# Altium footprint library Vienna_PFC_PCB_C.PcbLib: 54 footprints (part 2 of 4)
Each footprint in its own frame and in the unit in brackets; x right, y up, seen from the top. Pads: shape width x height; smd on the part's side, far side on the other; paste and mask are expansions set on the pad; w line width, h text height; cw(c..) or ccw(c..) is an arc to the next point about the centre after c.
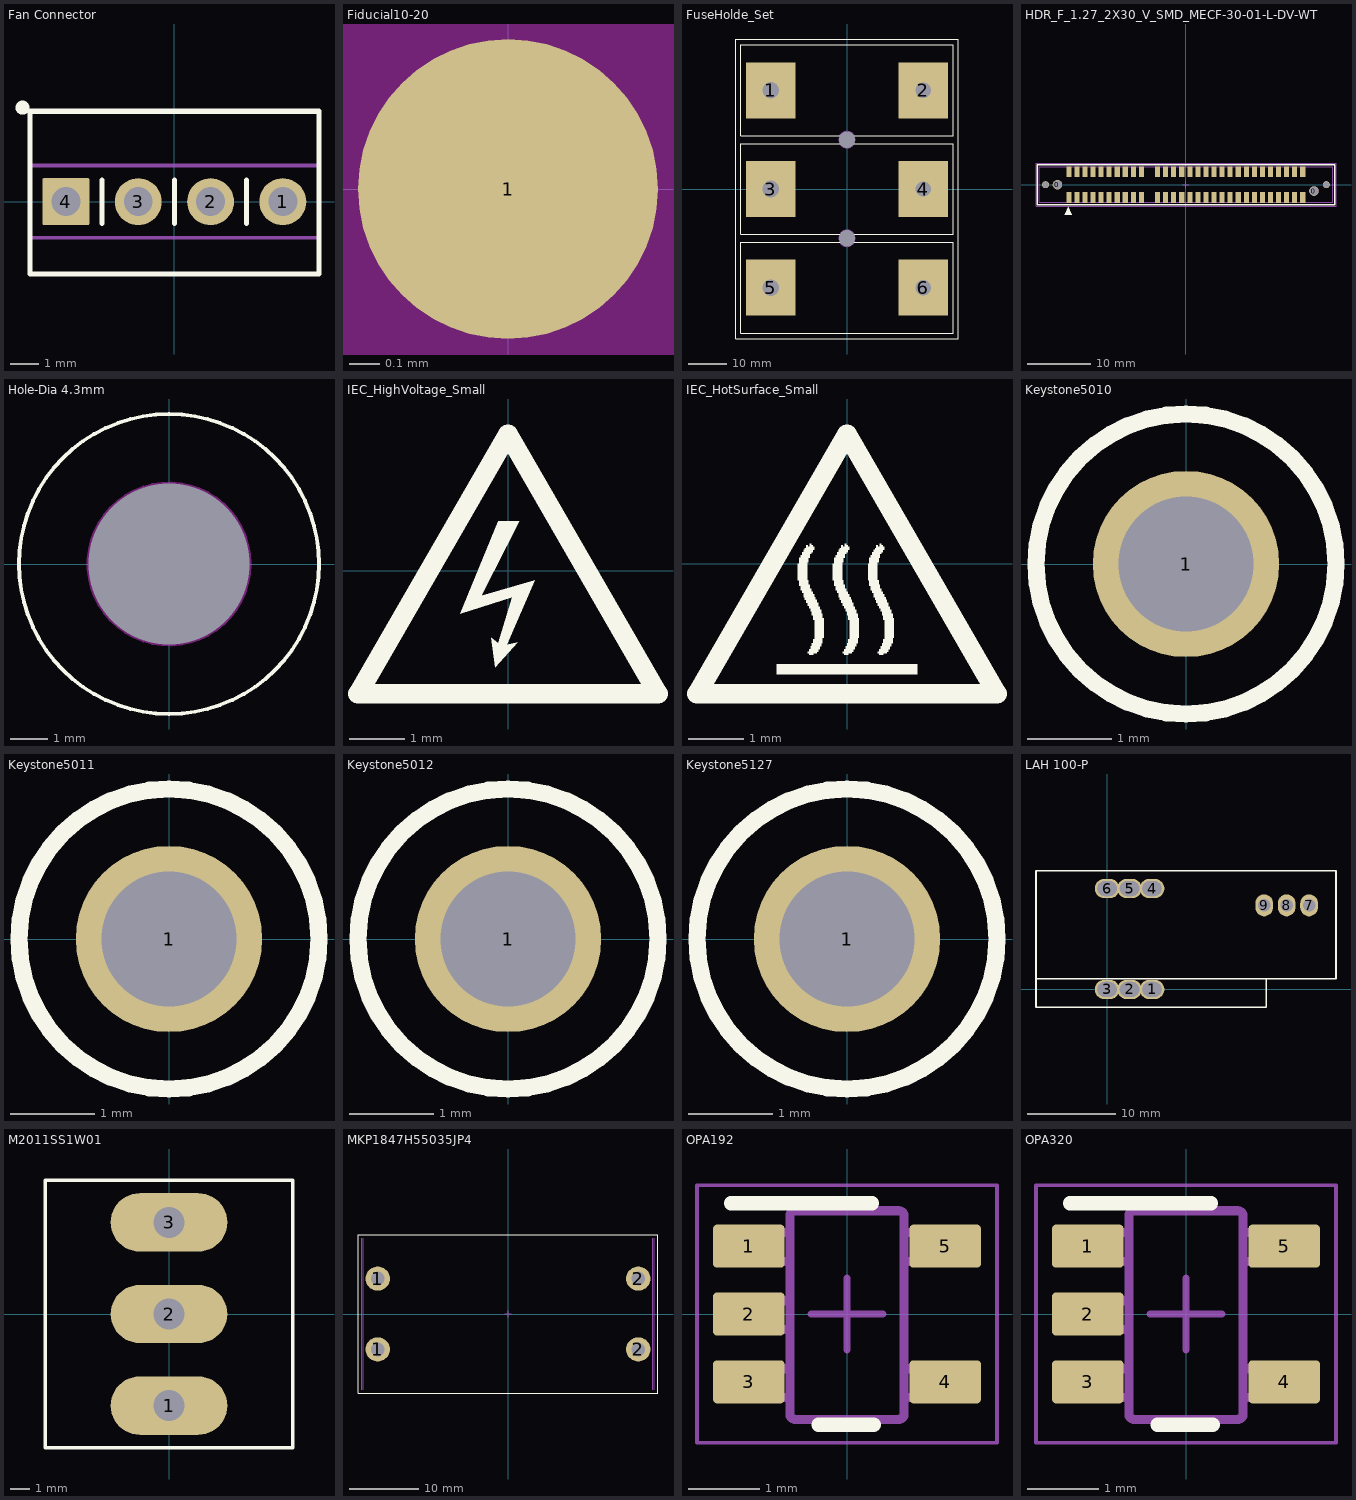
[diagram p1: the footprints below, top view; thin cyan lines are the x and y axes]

## Fan Connector [mm]
height 8.382
pads (4):
  round 1.65 hole 1.016: 1(3.81,0) 2(1.27,0) 3(-1.27,0)
  rrect6% 1.65x1.65 hole 1.016: 4(-3.81,0)
Top Overlay:
  circle w0.25: c-5.334,3.302 r0.125
  lines w0.178: -2.54,-2.54 2.54,-2.54 ; -2.54,-0.762 -2.54,0.762 ; -2.54,3.175 2.54,3.175 ; 0,-0.762 0,0.762 ; 2.54,-0.762 2.54,0.762 ; -5.08,-2.54 -5.08,3.175 0,3.175 5.08,3.175 5.08,-1.27 5.08,-2.54 -5.08,-2.54
Mechanical 5:
  lines w0.127: -5.08,-1.27 -5.08,1.27 5.08,1.27 5.08,-1.27 -5.08,-1.27
3D body: height 8, standoff 0, extent -4.064,1.27 4.064,3.048
3D body: height 2.54, standoff 0, extent -5.079,-1.269 -0.001,1.269
3D body: height 2.54, standoff 0, extent 0.001,-1.269 5.08,1.27
3D body: height 8.38, standoff -2.03, extent -1.587,-0.317 -0.953,0.317
3D body: height 8.38, standoff -2.03, extent 0.953,-0.317 1.587,0.317

## Fiducial10-20 [mm]
height 10.5
pads (1):
  round 1 smd mask+0.5: 1(0,0)
Top Layer keep-out:
  circle w1.178: c0,0 r0.5

## FuseHolde_Set [mm]
height 22.6
pads (8):
  round 0 hole 4.3: 0(0,-12.945) 0(0,12.954)
  rect 13x14.7 hole 4.4: 1(-20,25.908) 3(-20,0) 5(-20,-25.908)
  rect 13x14.7 hole 4: 2(20,25.908) 4(20,0) 6(20,-25.908)
Top Overlay:
  lines w0.2: -29.21,-39.37 -29.21,39.37 29.21,39.37 29.21,-39.37 -29.21,-39.37 ; -27.94,-37.846 27.94,-37.846 27.94,-13.97 -27.94,-13.97 -27.94,-37.846 ; -27.94,-11.938 -27.94,11.938 27.94,11.938 27.94,-11.938 -27.94,-11.938 ; -27.94,13.97 27.94,13.97 27.94,37.846 -27.94,37.846 -27.94,13.97
Mechanical 1:
  circle w0.013: c0,12.954 r2.15
  circle w0.013: c0,-12.945 r2.15
3D body: height 12, standoff 0, extent 16.614,-4.447 23.114,4.447
3D body: height 12, standoff 0, extent -23.368,-4.447 -16.868,4.447
3D body: height 12, standoff 0, extent -23.368,21.461 -16.868,30.355
3D body: height 12, standoff 0, extent 16.614,21.461 23.114,30.355
3D body: height 12, standoff 0, extent -23.368,-30.355 -16.868,-21.461
3D body: height 12, standoff 0, extent 16.614,-30.355 23.114,-21.461
3D body "User Library-51x14mm_fuse.STEP": height 19, standoff 5, extent -25.396,18.908 25.604,32.908
3D body "User Library-51x14mm_fuse.STEP": height 19, standoff 5, extent -25.65,-7 25.35,7
3D body "User Library-51x14mm_fuse.STEP": height 19, standoff 5, extent -25.396,-32.908 25.604,-18.908
3D body "M4_Screws.STEP": height 3.78, standoff -14.72, extent -4.602,8.45 4.398,17.45
3D body "M4_Screws.STEP": height 3.78, standoff -14.72, extent -4.424,-17.484 4.576,-8.484

## HDR_F_1.27_2X30_V_SMD_MECF-30-01-L-DV-WT [mm]
pads (62):
  round 1.1 hole 1 unplated mask+0.075: 0(-22.075,0) 0(22.125,0)
  round 1.5 hole 1.4 unplated mask+0.075: 0(-20.2,0) 0(20.175,-1)
  rect 0.8x1.7 smd mask+0.075: 1(-18.41,-2.01) 2(-18.41,2.05) 3(-17.14,-2.01) 4(-17.14,2.05) 5(-15.87,-2.01) 6(-15.87,2.05) 7(-14.6,-2.01) 8(-14.6,2.05) 9(-13.33,-2.01) 10(-13.33,2.05) 11(-12.06,-2.01) 12(-12.06,2.05) 13(-10.79,-2.01) 14(-10.79,2.05) 15(-9.52,-2.01) 16(-9.52,2.05) 17(-8.25,-2.01) 18(-8.25,2.05) 19(-6.98,-2.01) 20(-6.98,2.05) 23(-4.44,-2.01) 24(-4.44,2.05) 25(-3.17,-2.01) 26(-3.17,2.05) 27(-1.9,-2.01) 28(-1.9,2.05) 29(-0.63,-2.01) 30(-0.63,2.05) 31(0.64,-2.01) 32(0.64,2.05) 33(1.91,-2.01) 34(1.91,2.05) 35(3.18,-2.01) 36(3.18,2.05) 37(4.45,-2.01) 38(4.45,2.05) 39(5.72,-2.01) 40(5.72,2.05) 41(6.99,-2.01) 42(6.99,2.05) 43(8.26,-2.01) 44(8.26,2.05) 45(9.53,-2.01) 46(9.53,2.05) 47(10.8,-2.01) 48(10.8,2.05) 49(12.07,-2.01) 50(12.07,2.05) 51(13.34,-2.01) 52(13.34,2.05) 53(14.61,-2.01) 54(14.61,2.05) 55(15.88,-2.01) 56(15.88,2.05) 57(17.15,-2.01) 58(17.15,2.05) 59(18.42,-2.01) 60(18.42,2.05)
Top Overlay:
  region: -19.025,-4.75 -17.925,-4.75 -18.475,-3.5
  lines w0.2: -23.35,-3.175 23.425,-3.175 23.425,3.175 -23.35,3.175 -23.35,-3.175
Mechanical 11:
  lines w0.1: -23.1,-2.796 23.175,-2.796 23.175,2.796 -23.1,2.796 -23.1,-2.796
  text "1" at -18.525,-2.45 h1
  text "'.Designator'" at -1.2,-0.4 h1
Mechanical 15:
  lines w0.1: -0.5,0 0.5,0 ; 0,-0.5 0,0.5 ; -23.575,-3.4 23.65,-3.4 23.65,3.4 -23.575,3.4 -23.575,-3.4
3D body "MECF-30-01-L-DV-WT.stp": height 8.76, standoff -1.48, extent -23.1,-2.796 23.179,2.796

## Hole-Dia 4.3mm [mm] "Hole-Dia 4.3mm"
height 1
pads (1):
  round 0 hole 4.3: 0(0,0)
Top Overlay:
  circle w0.1: c0,0 r4
Keep-Out Layer:
  circle w0.1: c0,0 r2.15

## IEC_HighVoltage_Small [mm]
height 10.5
Top Overlay:
  region: -0.178,0.889 0.203,0.889 -0.483,-0.457 0.483,-0.178 -0.025,-1.346 0.178,-1.295 -0.229,-1.753 -0.305,-1.219 -0.178,-1.321 0.076,-0.483 -0.864,-0.787
  lines w0.356: -2.718,-2.235 0,2.472 2.718,-2.235 -2.718,-2.235

## IEC_HotSurface_Small [mm]
height 25.4
Top Overlay:
  drawing of 10 lines, arcs and shapes, not listed

## Keystone5010 [mil] "Keystone Multipurpose loops"
height 320
pads (1):
  round 87 hole 63: 1(0,0)
Top Overlay:
  circle w7.99: c0,0 r70
Mechanical 5:
  circle w5: c0,0 r69.46
3D body "Keystone_5010.stp": height 318.9, standoff -125.98, extent -63,-63.5 62.74,62.49

## Keystone5011 [mil] "Keystone Multipurpose loops"
height 320
pads (1):
  round 87 hole 63: 1(0,0)
Top Overlay:
  circle w7.99: c0,0 r70
Mechanical 5:
  circle w5: c0,0 r69.46
3D body "Keystone_5011.stp": height 318.9, standoff -125.98, extent -63,-63.5 62.74,62.49

## Keystone5012 [mil] "Keystone Multipurpose loops"
height 320
pads (1):
  round 87 hole 63: 1(0,0)
Top Overlay:
  circle w7.99: c0,0 r70
Mechanical 5:
  circle w5: c0,0 r69.46
3D body "Keystone_5012.stp": height 318.9, standoff -125.98, extent -63,-63.5 62.74,62.49

## Keystone5127 [mil] "Keystone Multipurpose loops"
height 320
pads (1):
  round 87 hole 63: 1(0,0)
Top Overlay:
  circle w7.99: c0,0 r70
Mechanical 5:
  circle w5: c0,0 r69.46
3D body "Keystone_5127.stp": height 318.9, standoff -125.98, extent -63,-63.5 62.74,62.49

## LAH 100-P [mm] "Inductor"
height 24
pads (9):
  oval 2.8x2.2 hole 1.7 slot 2.2 at 0 deg: 1(5.08,0) 2(2.54,0) 3(0,0) 4(5.08,11.43) 5(2.54,11.43) 6(0,11.43)
  oval 2x2.5 hole 1.4: 7(22.86,9.525) 8(20.32,9.525) 9(17.78,9.525)
Top Overlay:
  lines w0.178: -7.964,1.23 25.908,1.23 ; 18.034,1.23 18.034,-2.032 -8.052,-2.032 -8.052,13.462 25.908,13.462 25.908,1.27
3D body "LAH 100-P_blackbox.stp": height 21.05, standoff -4.9, extent -7.76,-1.731 25.54,13.208

## M2011SS1W01 [mm] "Capacitor"
height 34
pads (3):
  oval 6x3 hole 1.6 square: 1(0,-4.7) 2(0,0) 3(0,4.7)
Top Overlay:
  lines w0.178: -6.35,-6.858 6.35,-6.858 6.35,6.858 -6.35,6.858 -6.35,-6.858
Mechanical 15:
  lines w0.1: -0.5,0 0.5,0 ; 0,-0.5 0,0.5
3D body "M2011SS1W01.stp": height 28.88, standoff -4.67, extent -6.019,-6.509 5.97,6.495

## MKP1847H55035JP4 [mm] "Capacitor"
height 38.5
pads (4):
  round 3.5 hole 2: 1(-18.75,-5.1) 1(-18.75,5.1) 2(18.75,-5.1) 2(18.75,5.1)
Top Overlay:
  lines w0.178: -21.59,-11.43 21.59,-11.43 21.59,11.43 -21.59,11.43 -21.59,-11.43
Mechanical 13:
  lines w0.1: -21.082,-10.922 -21.082,10.922 ; -20.828,-10.922 -20.828,10.922 ; 20.828,-10.922 20.828,10.922 ; 21.082,-10.922 21.082,10.922
Mechanical 15:
  lines w0.1: -0.5,0 0.5,0 ; 0,-0.5 0,0.5
3D body: height 2.8, standoff 0, extent -21.116,-10.922 -20.828,10.922
3D body "MKP1847H55035+P4.step": height 39, standoff -6, extent -21.35,-11.1 21.35,11.1
3D body: height 2.8, standoff 0, extent -21.082,-4.318 -20.828,4.318
3D body: height 2.8, standoff 0, extent 20.828,-4.318 21.082,4.318
3D body: height 2.8, standoff 0, extent 20.794,-10.922 21.082,10.922

## OPA192 [mm] "SOT23, 5-Leads, Body 2.9x1.6mm, Pitch 0.95mm, Lead Span 2.8mm, IPC Medium Density"
height 1.45
pads (5):
  rrect17% 1x0.6 smd: 1(-1.375,0.95) 2(-1.375,0) 3(-1.375,-0.95) 4(1.375,-0.95) 5(1.375,0.95)
Top Overlay:
  lines w0.2: -1.625,1.55 0.35,1.55 ; -0.4,-1.55 0.375,-1.55
Mechanical 5:
  lines w0.127: -0.801,1.371 cw(c-0.725,1.37) -0.725,1.446 ; -0.801,1.37 -0.801,1.371 ; -0.801,1.37 -0.801,-1.399 -0.801,-1.4 ccw(c-0.725,-1.399) -0.725,-1.475 ; -0.725,-1.475 0.723,-1.475 0.724,-1.475 ccw(c0.723,-1.399) 0.799,-1.4 0.799,-1.399 0.799,1.37 ; -0.725,-1.475 -0.725,-1.475 ; -0.725,1.446 -0.725,1.446 ; -0.725,1.446 0.723,1.446 0.724,1.446 cw(c0.723,1.37) 0.799,1.371 ; 0.799,1.37 0.799,1.371 ; -1.423,-1.167 -1.423,-0.767 -1.199,-0.767 -1.105,-0.767 -1.088,-0.767 -0.835,-0.767 -0.801,-0.767 -0.801,-1.167 -0.835,-1.167 -1.088,-1.167 -1.105,-1.167 -1.199,-1.167 -1.423,-1.167 ; -1.423,-0.215 -1.423,0.186 -1.199,0.186 -1.105,0.186 -1.088,0.186 -0.835,0.186 -0.801,0.186 -0.801,-0.215 -0.835,-0.215 -1.088,-0.215 -1.105,-0.215 -1.199,-0.215 -1.423,-0.215 ; -1.423,0.738 -1.423,1.138 -1.199,1.138 -1.105,1.138 -1.088,1.138 -0.835,1.138 -0.801,1.138 -0.801,0.738 -0.835,0.738 -1.088,0.738 -1.105,0.738 -1.199,0.738 -1.423,0.738 ; 0.799,-1.167 0.834,-1.167 1.087,-1.167 1.103,-1.167 1.198,-1.167 1.422,-1.167 1.422,-0.767 1.198,-0.767 1.103,-0.767 1.087,-0.767 0.834,-0.767 0.799,-0.767 0.799,-1.167 ; 0.799,0.738 0.834,0.738 1.087,0.738 1.103,0.738 1.198,0.738 1.422,0.738 1.422,1.138 1.198,1.138 1.103,1.138 1.087,1.138 0.834,1.138 0.799,1.138 0.799,0.738
Mechanical 15:
  lines w0.05: -2.1,-1.8 -2.1,1.8 2.1,1.8 2.1,-1.8 -2.1,-1.8
  lines w0.1: -0.5,0 0.5,0 ; 0,-0.5 0,0.5
3D body "DBV0005A.stp": height 1.09, standoff 0, extent -1.422,-1.46 1.422,1.461

## OPA320 [mm] "SOT23, 5-Leads, Body 2.9x1.6mm, Pitch 0.95mm, Lead Span 2.8mm, IPC Medium Density"
height 1.45
pads (5):
  rrect17% 1x0.6 smd: 1(-1.375,0.95) 2(-1.375,0) 3(-1.375,-0.95) 4(1.375,-0.95) 5(1.375,0.95)
Top Overlay:
  lines w0.2: -1.625,1.55 0.35,1.55 ; -0.4,-1.55 0.375,-1.55
Mechanical 5:
  lines w0.127: -0.801,1.371 cw(c-0.725,1.37) -0.725,1.446 ; -0.801,1.37 -0.801,1.371 ; -0.801,1.37 -0.801,-1.399 -0.801,-1.4 ccw(c-0.725,-1.399) -0.725,-1.475 ; -0.725,-1.475 0.723,-1.475 0.724,-1.475 ccw(c0.723,-1.399) 0.799,-1.4 0.799,-1.399 0.799,1.37 ; -0.725,-1.475 -0.725,-1.475 ; -0.725,1.446 -0.725,1.446 ; -0.725,1.446 0.723,1.446 0.724,1.446 cw(c0.723,1.37) 0.799,1.371 ; 0.799,1.37 0.799,1.371 ; -1.423,-1.167 -1.423,-0.767 -1.199,-0.767 -1.105,-0.767 -1.088,-0.767 -0.835,-0.767 -0.801,-0.767 -0.801,-1.167 -0.835,-1.167 -1.088,-1.167 -1.105,-1.167 -1.199,-1.167 -1.423,-1.167 ; -1.423,-0.215 -1.423,0.186 -1.199,0.186 -1.105,0.186 -1.088,0.186 -0.835,0.186 -0.801,0.186 -0.801,-0.215 -0.835,-0.215 -1.088,-0.215 -1.105,-0.215 -1.199,-0.215 -1.423,-0.215 ; -1.423,0.738 -1.423,1.138 -1.199,1.138 -1.105,1.138 -1.088,1.138 -0.835,1.138 -0.801,1.138 -0.801,0.738 -0.835,0.738 -1.088,0.738 -1.105,0.738 -1.199,0.738 -1.423,0.738 ; 0.799,-1.167 0.834,-1.167 1.087,-1.167 1.103,-1.167 1.198,-1.167 1.422,-1.167 1.422,-0.767 1.198,-0.767 1.103,-0.767 1.087,-0.767 0.834,-0.767 0.799,-0.767 0.799,-1.167 ; 0.799,0.738 0.834,0.738 1.087,0.738 1.103,0.738 1.198,0.738 1.422,0.738 1.422,1.138 1.198,1.138 1.103,1.138 1.087,1.138 0.834,1.138 0.799,1.138 0.799,0.738
Mechanical 15:
  lines w0.05: -2.1,-1.8 -2.1,1.8 2.1,1.8 2.1,-1.8 -2.1,-1.8
  lines w0.1: -0.5,0 0.5,0 ; 0,-0.5 0,0.5
3D body "DBV0005A.stp": height 1.09, standoff 0, extent -1.422,-1.46 1.422,1.461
